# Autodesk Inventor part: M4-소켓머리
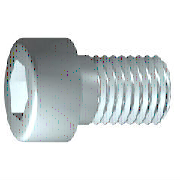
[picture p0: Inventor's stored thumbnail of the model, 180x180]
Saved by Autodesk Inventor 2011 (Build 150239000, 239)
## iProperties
IsCustomPart: 0
Created: 2009-02
Part Number: M4-소켓머리
Material: 강, 연강
Description: 6각머리 태핑 나사
Document SubType Name: Modeling
Standard: KS B 1003
Designer: 한국산업디자인학원 [http://gmhk.co.kr]
Standards Organization: KS
Language: ko-KR
Size Designation: M 4 x 12
Categories: <MemberInstance><Categories><Category DisplayName="조임쇠" InternalName="e4da775c-781d-43d5-af7c-5136215cf5a6" Mnemonic="FSTN"><Category DisplayName="볼트" InternalN
Density: 1 g/cm^3
Author: pww
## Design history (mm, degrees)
workplane "Work Plane1"
fillet "Fillet2" dims "d30" = 0.1 (= R)
revolve "본체" stored, may be unused: angle "d10" = 90 deg
sketch "스케치2"
  geometry: L1 (0, -4.9)-(0, 4.9) reference; L2 (-4.9, 0)-(4.9, 0) reference; L3 (1.732, 0)-(0.866, -1.5); L4 (0.866, -1.5)-(-0.866, -1.5); L5 (-0.866, -1.5)-(-1.732, 0); L6 (-1.732, 0)-(-0.866, 1.5); L7 (-0.866, 1.5)-(0.866, 1.5); L8 (0.866, 1.5)-(1.732, 0); 2 further points
  constraints: 12 end point, 1 coincident, 1 horizontal alignment, 1 point on line, 12 other
extrude "슬롯" join sketch "스케치2" stored distance "d11" = 10; taper "d12" = 0 deg
body "Solid1"
fillet "모깎기1" dims "d17" = 0.4 (= RR)
feature "스레드" dims "d13" = 10.25 (= GEL), "d14" = 0
chamfer "모따기1" distance "d15" = 0.42941 (= -0.5 x SPD + 0.5 x GD); stored, may be unused: second distance "d16" = 0.42941 (= GUL), angle "d27" = 45 deg
sketch "스케치1"
  geometry: L1 (-1, 0)-(12, 0); L2 (12, 0)-(12, 2); L3 (12, 2)-(1.75, 2); L4 (1.75, 2)-(1.32, 2); L5 (1.32, 2)-(0, 2); L6 (0, 2)-(0, 3.5); L7 (0, 3.5)-(-4, 3.5); L8 (-4, 3.5)-(-4, 1.732); L9 (-4, 1.732)-(-2, 1.732); L10 (-2, 1.732)-(-1, 0); L11 (-7.2, 0)-(15.2, 0) reference; L12 (0, -0.7)-(0, 4.2) reference; L13 (1.75, 2)-(0, 2)
  constraints: 22 end point, 6 parallel, 2 collinear, 2 perpendicular, 1 horizontal, 1 point on line
  dimensions: "d1" = 10.25 distance from line of L3.end L2 (= GEL); "d2" = 0.42952 distance of L4.end L3.end (computed from GAL); "d3" = 4 distance between parallel lines of L8 L6 (= KOH); "d4" = 2 distance of L8.end L9.end (= INTI); "d5" = 60 deg angle of L10 L1; "d6" = 4 diameter of L3 L1 (= GD); "d7" = 4 diameter of L5 L1 (= BDM); "d8" = 3.4641 diameter of L9 L1 (= 1.1547 x SW); "d9" = 7 diameter of L7 L1 (= KOD); "d26" = 12 distance between parallel lines of L12 L2 (= NLG)
other parameters: "GD" = 4 (= NND) [user parameter; used in 2 equation terms], "NLG" = 12 [user parameter; used in 1 equation term], "GEL" = 10.25 [user parameter; used in 2 equation terms], "KOD" = 7 [user parameter; used in 1 equation term], "KOH" = 4 [user parameter; used in 1 equation term], "INTI" = 2 [user parameter; used in 1 equation term], "GAL" = 0.42941 (= 0.61345 x PTC) [user parameter; used in 1 equation term], "GUL" = 0.42941 (= 0.61345 x PTC) [user parameter; used in 1 equation term], "BDM" = 4 (= NND) [user parameter; used in 1 equation term], "SW" = 3 [user parameter; used in 2 equation terms], "RR" = 0.4 [user parameter; used in 1 equation term], "SPD" = 3.14117 (= NND - 1.2269 x PTC) [user parameter; used in 1 equation term], "d19" = 0, "d28" = 0, "d29" = 0, "R" = 0.1 [user parameter; used in 1 equation term], "PHH" = 0.2 [user parameter], "GD1" = 3.14117 (= THREADDIA - 1.2269 x PTC) [user parameter], "THREADDIA" = 4 [user parameter; used in 1 equation term], "FAWI" = 45 deg [user parameter], "TPU" = 14.28571 (computed from PTC) [user parameter], "PTC" = 0.7 [user parameter; used in 5 equation terms], "NND" = 4 [user parameter; used in 3 equation terms], "TOA" = 30 deg [user parameter], "E0" = 3.465 (= 1.155 x SW) [user parameter]
